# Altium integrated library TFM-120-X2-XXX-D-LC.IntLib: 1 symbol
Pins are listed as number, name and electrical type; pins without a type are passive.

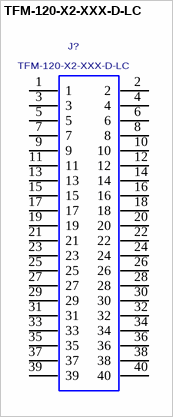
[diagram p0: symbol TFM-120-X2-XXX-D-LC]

## TFM-120-X2-XXX-D-LC
designator J?
0.050" TERMINAL STRIP, SURFACE MOUNT ASSEMBLY.; MANUFACTURER: SAMTEC
footprint TFM-120-X2-XXX-D-LC
pins: 1, 2, 3, 4, 5, 6, 7, 8, 9, 10, 11, 12, 13, 14, 15, 16, 17, 18, 19, 20, 21, 22, 23, 24, 25, 26, 27, 28, 29, 30, 31, 32, 33, 34, 35, 36, 37, 38, 39, 40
